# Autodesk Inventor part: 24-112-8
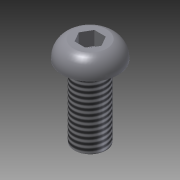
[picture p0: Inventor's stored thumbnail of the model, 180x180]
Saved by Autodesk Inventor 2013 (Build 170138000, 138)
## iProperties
Created: 2004-10
Part Number: 24-112-8
Material: Stahl (hohe Festigk., niedr. Legier.)
Document SubType Name: Modeling
Designer: Autodesk, Inc.
Manufacturer: Standard
Standards Organization: Custom
Description: SCREW, PARKER IPS, BUTTON HEAD, M8X12
Catalog Web Link: http://www.parker.com/ead/cm1.asp?cmid=809
Vendor: PARKER IPS
Mass: 10.8823 g
Surface Area: 9.37524 cm^2
Volume: 1.38805 cm^3
Density: 7.84 g/cm^3
CAGE: 1LJX3
Dept. ID: Product Design
Description #2: ---
Finish #1: ---
Finish #2: ---
Material ID: ---
Project Number: ---
Author: Autodesk, Inc.
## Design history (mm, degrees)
derived "2X-YYY-ZZ IPS Screws.ipt"
body "Solid1"
tag "TaggingFeature2"
feature "Solid1::2X-YYY-ZZ IPS Screws.ipt" dims "ScaleForDerivedMember" = 10
